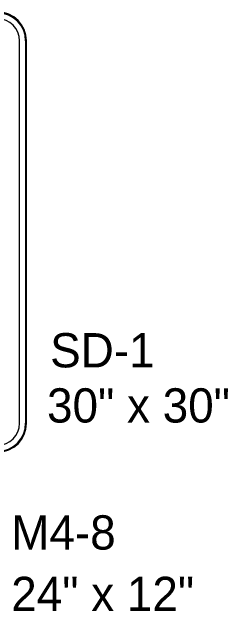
# Model space of a CAD drawing. Extents: x 2157572 to 5059327, y 715220 to 1674494.
# Drawn here: x 2165946 to 2166130, y 721024 to 721535 of the extents above; entities that cross this region are included whole.
import ezdxf

# ---------------------------------------------------------------- set-up
doc = ezdxf.new("R2010")
doc.units = 0
for name, color, linetype in [('Level 56', 7, 'Continuous'), ('Level 57', 7, 'Continuous'), ('Map Preparation County Base Location Boundary Shape', 7, 'Continuous'), ('Map Preparation County Base StatePlane Tick Mark', 7, 'Continuous'), ('Map Preparation County Inset Cut Line', 7, 'Continuous')]:
    doc.layers.add(name, color=color, linetype=linetype)

msp = doc.modelspace()

# ---------------------------------------------------------------- linework, layer by layer
at = {"layer": 'Map Preparation County Base Location Boundary Shape'}
for p, q in [((2165952.73, 721184.29), (2165952.73, 721510.07)), ((2165958.59, 721184.29), (2165958.59, 721510.07))]:
    msp.add_line(p, q, dxfattribs=at)
for centre, radius, start, end in [((2165933.98, 721510.07), 24.61, 0, 90), ((2165933.98, 721510.07), 18.75, 0, 90), ((2165933.98, 721184.29), 18.75, 270, 0), ((2165933.98, 721184.29), 24.61, 270, 0)]:
    msp.add_arc(centre, radius, start, end, dxfattribs=at)
at = {"layer": 'Map Preparation County Base StatePlane Tick Mark'}
for p, q in [((2165952.73, 721184.29), (2165952.73, 721510.07)), ((2165958.59, 721184.29), (2165958.59, 721510.07))]:
    msp.add_line(p, q, dxfattribs=at)
for centre, radius, start, end in [((2165933.98, 721510.07), 24.61, 0, 90), ((2165933.98, 721510.07), 18.75, 0, 90), ((2165933.98, 721184.29), 18.75, 270, 0), ((2165933.98, 721184.29), 24.61, 270, 0)]:
    msp.add_arc(centre, radius, start, end, dxfattribs=at)
at = {"layer": 'Map Preparation County Inset Cut Line'}
for p, q in [((2165952.73, 721184.29), (2165952.73, 721510.07)), ((2165957.81, 721510.07), (2165957.81, 721184.29)), ((2165958.59, 721184.29), (2165958.59, 721510.07)), ((2165958.59, 721184.29), (2165958.59, 721510.07))]:
    msp.add_line(p, q, dxfattribs=at)
for centre, radius, start, end in [((2165933.98, 721510.07), 24.61, 0, 90), ((2165933.98, 721510.07), 24.61, 0, 90), ((2165933.98, 721510.07), 23.83, 0, 90), ((2165933.98, 721510.07), 18.75, 0, 90), ((2165933.98, 721184.29), 24.61, 270, 0), ((2165933.98, 721184.29), 18.75, 270, 0), ((2165933.98, 721184.29), 24.61, 270, 0), ((2165933.98, 721184.29), 23.83, 270, 0)]:
    msp.add_arc(centre, radius, start, end, dxfattribs=at)

# ---------------------------------------------------------------- texts
at = {"layer": 'Level 56'}
for s, p in [('SD-1', (2165978.72, 721231.93)), ('30" x 30"', (2165976.09, 721184.93))]:
    msp.add_text(s, height=29.18, rotation=360, dxfattribs=at).set_placement(p)
at = {"layer": 'Level 57'}
for s, p in [('M4-8', (2165945.61, 721076.73)), ('24" x 12"', (2165945.61, 721024.38))]:
    msp.add_text(s, height=29.18, rotation=360, dxfattribs=at).set_placement(p)

doc.saveas('drawing.dxf')
